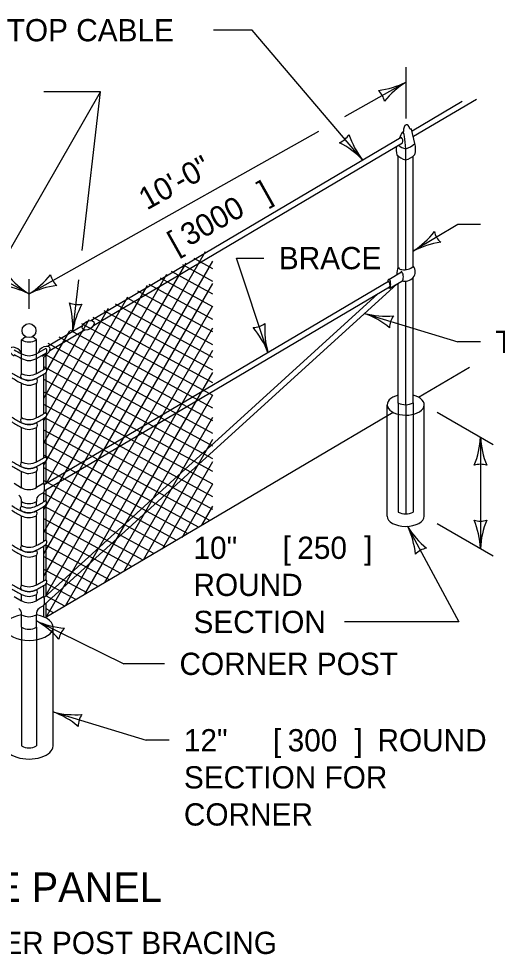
# Model space of a CAD drawing. Extents: x 49973.1 to 50021, y 49987.6 to 50015.4.
# Drawn here: x 49974.681 to 49975.97, y 50010.322 to 50012.844 of the extents above; entities that cross this region are included whole.
import ezdxf

# ---------------------------------------------------------------- set-up
doc = ezdxf.new("R2010")
doc.units = 0
for name, color, linetype in [('Level 1', 7, 'Continuous'), ('Level 2', 7, 'Continuous'), ('Level 3', 7, 'Continuous'), ('Level 4', 7, 'Continuous')]:
    doc.layers.add(name, color=color, linetype=linetype)

msp = doc.modelspace()

# ---------------------------------------------------------------- linework, layer by layer
at = {"layer": 'Level 1'}
for p, q in [((49975.7408, 50012.5423), (49975.8759, 50012.6222)), ((49975.7447, 50012.5273), (49975.9146, 50012.6278)), ((49975.7477, 50012.5078), (49975.7393, 50012.5467)), ((49974.875, 50012.0307), (49975.7109, 50012.5247)), ((49974.8821, 50012.0174), (49975.7149, 50012.5097)), ((49975.7235, 50012.1676), (49975.7235, 50012.4935)), ((49975.7035, 50012.1739), (49975.7035, 50012.4739)), ((49975.7435, 50012.1762), (49975.7435, 50012.4739)), ((49974.7487, 50011.4603), (49975.1844, 50012.2164)), ((49974.7487, 50011.4013), (49975.204, 50012.1903)), ((49974.7487, 50011.5207), (49975.1319, 50012.1857)), ((49975.204, 50012.1704), (49975.1532, 50012.1981)), ((49975.204, 50012.102), (49975.0927, 50012.1628)), ((49975.204, 50012.1362), (49975.1229, 50012.1804)), ((49975.6778, 50012.1417), (49975.7118, 50012.1618)), ((49974.7488, 50011.3416), (49975.204, 50012.1304)), ((49974.7493, 50011.5884), (49975.6773, 50012.1369)), ((49974.7553, 50011.5919), (49975.0798, 50012.1552)), ((49975.204, 50012.0679), (49975.0625, 50012.1451)), ((49975.6805, 50012.1181), (49975.7128, 50012.1372)), ((49975.7035, 50011.808), (49975.7035, 50012.1317)), ((49975.7235, 50011.8035), (49975.7235, 50012.1364)), ((49975.7435, 50011.8085), (49975.7435, 50012.1467)), ((49974.7487, 50011.6411), (49975.0275, 50012.1247)), ((49975.7002, 50012.1298), (49974.7491, 50011.264)), ((49974.7496, 50011.5712), (49975.6801, 50012.1211)), ((49975.204, 50011.9997), (49975.002, 50012.1098)), ((49975.204, 50012.0337), (49975.0322, 50012.1274)), ((49974.7487, 50011.7012), (49974.9752, 50012.0941)), ((49975.6481, 50012.1026), (49974.749, 50011.2842)), ((49975.204, 50011.9653), (49974.9718, 50012.0921)), ((49974.7487, 50011.7612), (49974.923, 50012.0636)), ((49974.7543, 50011.2911), (49975.204, 50012.0699)), ((49975.204, 50011.8966), (49974.9112, 50012.0567)), ((49975.204, 50011.9311), (49974.9415, 50012.0744)), ((49974.7487, 50011.8213), (49974.8709, 50012.0332)), ((49975.204, 50011.8626), (49974.881, 50012.0391)), ((49974.7543, 50011.2312), (49975.204, 50012.0106)), ((49974.8528, 50012.0167), (49974.7585, 50011.9608)), ((49974.8594, 50012.0051), (49974.7644, 50011.9489)), ((49975.204, 50011.8284), (49974.8507, 50012.0214)), ((49974.6885, 50011.9783), (49974.6991, 50011.9872)), ((49974.7285, 50011.9783), (49974.7179, 50011.9872)), ((49974.7568, 50011.8956), (49974.8186, 50012.0026)), ((49975.204, 50011.7603), (49974.7901, 50011.986)), ((49975.204, 50011.7942), (49974.8204, 50012.0037)), ((49974.6885, 50011.8867), (49974.6885, 50011.9783)), ((49974.7285, 50011.8869), (49974.7285, 50011.9783)), ((49974.7542, 50011.9552), (49974.7291, 50011.9408)), ((49975.204, 50011.7258), (49974.76, 50011.9685)), ((49974.753, 50011.9416), (49974.7292, 50011.9281)), ((49974.7543, 50011.9352), (49974.7487, 50011.9319)), ((49974.7487, 50011.8977), (49974.7487, 50011.9319)), ((49975.204, 50011.6919), (49974.7503, 50011.9397)), ((49974.7543, 50011.9013), (49974.7543, 50011.9352)), ((49974.8066, 50011.2615), (49975.204, 50011.9508)), ((49975.204, 50011.6574), (49974.7487, 50011.9062)), ((49974.7968, 50011.9048), (49974.8036, 50011.9165)), ((49975.7577, 50011.8237), (49975.895, 50011.9049)), ((49974.7487, 50011.7788), (49974.7487, 50011.8851)), ((49974.7543, 50011.7822), (49974.7543, 50011.8891)), ((49974.859, 50011.2925), (49975.204, 50011.8908)), ((49974.6885, 50011.7675), (49974.6885, 50011.8616)), ((49974.7285, 50011.7678), (49974.7285, 50011.8612)), ((49975.204, 50011.6238), (49974.7487, 50011.872)), ((49975.204, 50011.589), (49974.7487, 50011.8379)), ((49974.9119, 50011.3238), (49975.204, 50011.8303)), ((49975.204, 50011.5553), (49974.7487, 50011.8038)), ((49975.6735, 50011.5035), (49975.6735, 50011.8035)), ((49975.7735, 50011.5035), (49975.7735, 50011.8035)), ((49974.7524, 50011.2295), (49975.6894, 50011.7834)), ((49974.7487, 50011.6599), (49974.7487, 50011.7661)), ((49975.204, 50011.5209), (49974.7514, 50011.768)), ((49974.7543, 50011.663), (49974.7543, 50011.7702)), ((49974.9638, 50011.3538), (49975.204, 50011.7705)), ((49974.6885, 50011.6485), (49974.6885, 50011.7423)), ((49974.7285, 50011.649), (49974.7285, 50011.7422)), ((49975.1957, 50011.4916), (49974.7487, 50011.7354)), ((49975.0166, 50011.3855), (49975.204, 50011.7106)), ((49975.1655, 50011.4737), (49974.7485, 50011.7013)), ((49975.1355, 50011.456), (49974.7481, 50011.6673)), ((49974.7543, 50011.5914), (49974.7543, 50011.6514)), ((49975.1054, 50011.4382), (49974.748, 50011.6333)), ((49974.7487, 50011.5901), (49974.7487, 50011.6473)), ((49975.0686, 50011.4154), (49975.204, 50011.6503)), ((49974.6885, 50011.5799), (49974.6885, 50011.6234)), ((49974.7285, 50011.5802), (49974.7285, 50011.623)), ((49974.6683, 50011.5917), (49974.6885, 50011.5799)), ((49974.7481, 50011.5917), (49974.7284, 50011.5801)), ((49975.0754, 50011.4205), (49974.7494, 50011.5984)), ((49975.1208, 50011.4459), (49975.204, 50011.5902)), ((49974.7484, 50011.5671), (49974.7358, 50011.5597)), ((49974.7487, 50011.5415), (49974.7487, 50011.568)), ((49975.0451, 50011.4025), (49974.7487, 50011.5645)), ((49974.7543, 50011.5431), (49974.7543, 50011.5739)), ((49974.6885, 50011.5292), (49974.6885, 50011.5423)), ((49974.7285, 50011.5302), (49974.7285, 50011.5425)), ((49974.7487, 50011.4345), (49974.7487, 50011.5284)), ((49975.0162, 50011.3844), (49974.7501, 50011.5296)), ((49974.7543, 50011.438), (49974.7543, 50011.533)), ((49975.1746, 50011.4791), (49975.204, 50011.5301)), ((49974.6885, 50011.4234), (49974.6885, 50011.504)), ((49974.7285, 50011.4238), (49974.7285, 50011.5044)), ((49974.9862, 50011.3666), (49974.7488, 50011.4962)), ((49974.9561, 50011.3488), (49974.7488, 50011.4619)), ((49974.9251, 50011.3316), (49974.7535, 50011.4251)), ((49974.7543, 50011.3317), (49974.7543, 50011.4257)), ((49974.7487, 50011.3282), (49974.7487, 50011.422)), ((49974.6885, 50011.3172), (49974.6885, 50011.3983)), ((49974.7285, 50011.3173), (49974.7285, 50011.398)), ((49974.895, 50011.3138), (49974.7489, 50011.3936)), ((49974.8649, 50011.296), (49974.7487, 50011.3594)), ((49974.7487, 50011.2849), (49974.7487, 50011.3157)), ((49974.7543, 50011.2891), (49974.7543, 50011.3195)), ((49974.8349, 50011.2783), (49974.7557, 50011.3214)), ((49974.6683, 50011.2865), (49974.6885, 50011.2747)), ((49974.6885, 50011.2746), (49974.6885, 50011.292)), ((49974.7481, 50011.2865), (49974.7284, 50011.2749)), ((49974.7285, 50011.275), (49974.7285, 50011.2919)), ((49974.8047, 50011.2604), (49974.7536, 50011.2884)), ((49974.7484, 50011.2619), (49974.7361, 50011.2546)), ((49974.7487, 50011.2318), (49974.7487, 50011.2628)), ((49974.7543, 50011.2313), (49974.7543, 50011.2686)), ((49974.7747, 50011.2427), (49974.7546, 50011.2536)), ((49974.6885, 50011.2035), (49974.6885, 50011.2371)), ((49974.7285, 50011.2035), (49974.7285, 50011.2373)), ((49974.7735, 50010.8835), (49974.7735, 50011.2035))]:
    msp.add_line(p, q, dxfattribs=at)
msp.add_circle((49974.7085, 50012.0034), 0.0188, dxfattribs=at)
for centre, radius, start, end in [((49975.7183, 50012.5302), 0.00892, 101.7957, 120.997), ((49975.7362, 50012.5502), 0.00296, 237.4787, 300.0955), ((49975.7463, 50012.5611), 0.016, 237.5014, 244.0751), ((49975.704, 50012.5148), 0.0121, 334.8948, 54.9962), ((49975.7611, 50012.4926), 0.0633, 173.4419, 193.7131), ((49975.7356, 50012.5413), 0.0492, 230.34, 255.8294), ((49975.7101, 50012.5439), 0.0521, 284.9196, 316.2234), ((49975.7004, 50012.4928), 0.0496, 342.4177, 17.5896), ((49975.7356, 50012.5113), 0.0492, 223.0922, 255.8294), ((49975.7101, 50012.5139), 0.0521, 284.9189, 316.2234), ((49975.7312, 50012.1585), 0.0317, 150.1806, 187.0158), ((49975.7132, 50012.178), 0.0102, 201.7798, 270.84), ((49975.7193, 50012.205), 0.0377, 260.9359, 311.2879), ((49975.7255, 50012.1621), 0.0237, 320.3364, 38.1248), ((49975.6879, 50012.1365), 0.0127, 160.71, 183.758), ((49975.6664, 50012.1268), 0.0149, 337.4474, 42.724), ((49975.7203, 50012.1672), 0.0309, 255.9694, 319.2134), ((49975.6835, 50012.121), 0.00599, 192.716, 219.6559), ((49974.7085, 50012.0141), 0.041, 240.8333, 299.1667), ((49974.7481, 50011.9489), 0.00871, 303.6425, 46.3366), ((49974.6963, 50011.8805), 0.0105, 142.1576, 216.9265), ((49974.7481, 50011.8952), 0.00871, 312.91, 46.3619), ((49974.7209, 50011.8678), 0.0105, 323.0735, 37.8424), ((49975.7231, 50011.8481), 0.0445, 244.0215, 297.414), ((49974.748, 50011.7762), 0.00871, 312.91, 46.3366), ((49974.6962, 50011.7615), 0.0105, 142.1576, 216.9265), ((49974.7208, 50011.7488), 0.0105, 323.0735, 37.8424), ((49974.7479, 50011.6572), 0.00871, 312.91, 46.3366), ((49974.6961, 50011.6425), 0.0105, 142.1576, 216.9265), ((49974.7207, 50011.6298), 0.0105, 323.0735, 37.8424), ((49974.7082, 50011.6159), 0.041, 239.6098, 300.3902), ((49974.7159, 50011.579), 0.0346, 339.9145, 21.52), ((49974.6705, 50011.5448), 0.0181, 352.1171, 54.7359), ((49974.7466, 50011.545), 0.0181, 125.2641, 187.8829), ((49974.6954, 50011.5234), 0.0105, 142.1576, 216.9265), ((49974.7084, 50011.5782), 0.041, 240.8333, 299.1667), ((49974.7472, 50011.5381), 0.00871, 312.91, 46.3366), ((49974.72, 50011.5107), 0.0105, 323.0735, 37.8424), ((49974.7481, 50011.432), 0.00871, 312.91, 46.3366), ((49974.6963, 50011.4173), 0.0105, 142.1576, 216.9265), ((49974.7209, 50011.4046), 0.0105, 323.0735, 37.8424), ((49974.7481, 50011.3257), 0.00871, 312.91, 46.3366), ((49974.6963, 50011.311), 0.0105, 142.1576, 216.9265), ((49974.7209, 50011.2983), 0.0105, 323.0735, 37.8424), ((49974.7082, 50011.3107), 0.041, 239.6098, 299.4812), ((49974.7159, 50011.2738), 0.0346, 339.9145, 21.52), ((49974.6705, 50011.2396), 0.0181, 352.1171, 54.7359), ((49974.7466, 50011.2398), 0.0181, 125.2641, 187.8829), ((49974.7084, 50011.273), 0.041, 240.8333, 299.1667), ((49974.7085, 50011.2394), 0.041, 240.8333, 299.1667)]:
    msp.add_arc(centre, radius, start, end, dxfattribs=at)
for centre, major_axis, ratio, start_param, end_param in [((49975.7262, 50012.5413), (-0.0001, 0.0176), 0.514964, 5.08229, 7.879337), ((49975.7123, 50012.1495), (-0.0005, 0.0123), 0.386165, 3.161585, 6.68335), ((49975.6782, 50012.1294), (-0.0005, 0.0123), 0.386165, 3.161585, 6.68335), ((49974.6719, 50011.9456), (-0.015, 0.009), 0.610393, 3.559041, 7.997344), ((49974.7495, 50011.9482), (0.015, 0.009), 0.610393, 4.569027, 9.084095), ((49974.7495, 50011.9482), (0.015, 0.009), 0.610393, 3.972008, 4.569027), ((49975.7235, 50011.8035), (0.05, 0), 0.560136, 1.982076, 7.431596), ((49975.7235, 50011.5035), (0.05, 0), 0.560136, 3.141593, 6.283185), ((49974.7085, 50011.2035), (0.065, 0), 0.543263, 1.885894, 7.541224), ((49974.7085, 50010.8835), (-0.065, 0), 0.54167, 0, 3.141593)]:
    msp.add_ellipse(centre, major_axis=major_axis, ratio=ratio, start_param=start_param, end_param=end_param, dxfattribs=at)
msp.add_ellipse((49974.8678, 50012.0178), major_axis=(0.015, 0.009), ratio=0.610393, dxfattribs=at)
for points in [[(49975.7235, 50012.4935), (49975.714, 50012.5373), (49975.7067, 50012.5222)], [(49975.7171, 50012.5408), (49975.7169, 50012.5395), (49975.7164, 50012.5389)], [(49974.6683, 50011.9516), (49974.6885, 50011.9408), (49974.7085, 50011.9355), (49974.7291, 50011.9408)], [(49974.6684, 50011.9389), (49974.6886, 50011.9281), (49974.7086, 50011.9228), (49974.7292, 50011.9281)], [(49974.663, 50011.8888), (49974.6885, 50011.8742), (49974.7085, 50011.8689), (49974.7291, 50011.8742)], [(49974.754, 50011.8888), (49974.7285, 50011.8742), (49974.7085, 50011.8689), (49974.6879, 50011.8742)], [(49974.7541, 50011.9015), (49974.7286, 50011.8869), (49974.7086, 50011.8816), (49974.688, 50011.8869)], [(49974.6631, 50011.8761), (49974.6886, 50011.8615), (49974.7086, 50011.8562), (49974.7292, 50011.8615)], [(49974.754, 50011.7825), (49974.7285, 50011.7679), (49974.7085, 50011.7626), (49974.6879, 50011.7679)], [(49974.6629, 50011.7698), (49974.6884, 50011.7552), (49974.7084, 50011.7499), (49974.729, 50011.7552)], [(49974.663, 50011.7571), (49974.6885, 50011.7425), (49974.7085, 50011.7372), (49974.7291, 50011.7425)], [(49974.7539, 50011.7698), (49974.7284, 50011.7552), (49974.7084, 50011.7499), (49974.6878, 50011.7552)], [(49974.7539, 50011.6635), (49974.7284, 50011.6489), (49974.7084, 50011.6436), (49974.6878, 50011.6489)], [(49974.6628, 50011.6508), (49974.6883, 50011.6362), (49974.7083, 50011.6309), (49974.7289, 50011.6362)], [(49974.6629, 50011.6381), (49974.6884, 50011.6235), (49974.7084, 50011.6182), (49974.729, 50011.6235)], [(49974.7538, 50011.6508), (49974.7283, 50011.6362), (49974.7083, 50011.6309), (49974.6877, 50011.6362)], [(49974.6621, 50011.5317), (49974.6876, 50011.5171), (49974.7076, 50011.5118), (49974.7282, 50011.5171)], [(49974.7531, 50011.5317), (49974.7276, 50011.5171), (49974.7076, 50011.5118), (49974.687, 50011.5171)], [(49974.7532, 50011.5444), (49974.7277, 50011.5298), (49974.7077, 50011.5245), (49974.6871, 50011.5298)], [(49974.6622, 50011.519), (49974.6877, 50011.5044), (49974.7077, 50011.4991), (49974.7283, 50011.5044)], [(49974.663, 50011.4256), (49974.6885, 50011.411), (49974.7085, 50011.4057), (49974.7291, 50011.411)], [(49974.754, 50011.4256), (49974.7285, 50011.411), (49974.7085, 50011.4057), (49974.6879, 50011.411)], [(49974.7541, 50011.4383), (49974.7286, 50011.4237), (49974.7086, 50011.4184), (49974.688, 50011.4237)], [(49974.6631, 50011.4129), (49974.6886, 50011.3983), (49974.7086, 50011.393), (49974.7292, 50011.3983)], [(49974.7541, 50011.332), (49974.7286, 50011.3174), (49974.7086, 50011.3121), (49974.688, 50011.3174)], [(49974.663, 50011.3193), (49974.6885, 50011.3047), (49974.7085, 50011.2994), (49974.7291, 50011.3047)], [(49974.6631, 50011.3066), (49974.6886, 50011.292), (49974.7086, 50011.2867), (49974.7292, 50011.292)], [(49974.754, 50011.3193), (49974.7285, 50011.3047), (49974.7085, 50011.2994), (49974.6879, 50011.3047)]]:
    msp.add_spline(points, degree=3, dxfattribs=at)
at = {"layer": 'Level 3'}
for p, q in [((49975.3101, 50012.8135), (49975.2054, 50012.8135)), ((49975.6074, 50012.4636), (49975.3101, 50012.8135)), ((49975.7243, 50012.5751), (49975.7243, 50012.7137)), ((49975.5593, 50012.5808), (49975.7241, 50012.6736)), ((49974.6381, 50012.188), (49974.9013, 50012.6472)), ((49974.9013, 50012.6472), (49974.7483, 50012.6472)), ((49974.8514, 50012.2197), (49974.9013, 50012.6472)), ((49974.8817, 50012.1996), (49975.4896, 50012.5416)), ((49975.8636, 50012.2893), (49975.7435, 50012.2176)), ((49975.9248, 50012.2893), (49975.8636, 50012.2893)), ((49974.7085, 50012.1022), (49974.8817, 50012.1996)), ((49975.3522, 50011.9447), (49975.268, 50012.199)), ((49975.268, 50012.199), (49975.3416, 50012.199)), ((49974.6013, 50012.1629), (49974.7085, 50012.1022)), ((49974.7085, 50012.0622), (49974.7085, 50012.1422)), ((49974.8422, 50012.1402), (49974.8259, 50012.0008)), ((49975.6126, 50012.05), (49975.8636, 50011.9735)), ((49975.9248, 50011.9735), (49975.8636, 50011.9735)), ((49975.8082, 50011.7836), (49975.9595, 50011.6963)), ((49975.9248, 50011.7164), (49975.9248, 50011.4164)), ((49975.7286, 50011.4757), (49975.8669, 50011.2179)), ((49975.8082, 50011.4836), (49975.9595, 50011.3963)), ((49974.7285, 50011.2206), (49974.9642, 50011.105)), ((49975.8669, 50011.2179), (49975.559, 50011.2179)), ((49975.074, 50011.105), (49974.9642, 50011.105)), ((49974.7735, 50010.9754), (49975.0246, 50010.8989)), ((49975.0858, 50010.8989), (49975.0246, 50010.8989))]:
    msp.add_line(p, q, dxfattribs=at)
for centre, radius, start, end in [((49975.6234, 50012.8718), 0.2223, 276.8182, 297.0017), ((49975.8485, 50012.4765), 0.233, 122.1895, 141.4393), ((49975.6126, 50012.6109), 0.0548, 11.501, 47.2234), ((49975.5236, 50012.5606), 0.0548, 292.973, 328.6954), ((49975.4389, 50012.3027), 0.233, 43.6615, 62.9114), ((49975.7815, 50012.6019), 0.2223, 198.2902, 218.4737), ((49975.6161, 50012.4127), 0.233, 303.1681, 322.418), ((49975.8542, 50012.2824), 0.0548, 192.4796, 228.202), ((49975.8479, 50012.0213), 0.2223, 97.7968, 117.9804), ((49974.8259, 50012.2911), 0.2223, 217.9705, 238.154), ((49974.5844, 50012.2994), 0.233, 302.1914, 321.4413), ((49974.8203, 50012.1651), 0.0548, 191.503, 227.2253), ((49974.604, 50011.894), 0.233, 63.3418, 82.5916), ((49974.8095, 50011.9041), 0.2223, 96.8201, 117.0037), ((49974.84, 50012.1282), 0.0548, 245.8148, 281.5372), ((49974.5933, 50012.015), 0.233, 356.5033, 15.7531), ((49975.0457, 50011.9672), 0.2223, 151.132, 171.3155), ((49975.5363, 50011.8412), 0.2223, 49.7405, 69.924), ((49975.6725, 50012.2752), 0.233, 255.1118, 274.3617), ((49975.7348, 50012.011), 0.0548, 144.4233, 180.1457), ((49975.3119, 50012.0665), 0.0548, 270.449, 306.1713), ((49975.1349, 50011.8607), 0.233, 21.1375, 40.3873), ((49975.566, 50012.0058), 0.2223, 175.7662, 195.9497), ((49975.7027, 50011.7255), 0.2223, 337.456, 357.6395), ((49976.1576, 50011.7278), 0.233, 182.8273, 202.0772), ((49975.9248, 50011.5881), 0.0548, 72.1388, 107.8612), ((49975.5285, 50011.3788), 0.2223, 5.6616, 25.8451), ((49975.9283, 50011.5958), 0.233, 211.0329, 230.2828), ((49975.9248, 50011.5446), 0.0548, 252.1388, 287.8612), ((49975.6921, 50011.4049), 0.233, 2.8273, 22.0772), ((49976.147, 50011.4072), 0.2223, 157.456, 177.6395), ((49975.7892, 50011.3627), 0.0548, 100.3444, 136.0668), ((49974.6199, 50011.0266), 0.2223, 40.5672, 60.7507), ((49974.8235, 50011.4333), 0.233, 245.9385, 265.1884), ((49974.8429, 50011.1626), 0.0548, 135.25, 170.9724), ((49974.6972, 50010.7666), 0.2223, 49.7405, 69.924), ((49974.8334, 50011.2006), 0.233, 255.1118, 274.3617), ((49974.8957, 50010.9364), 0.0548, 144.4233, 180.1457)]:
    msp.add_arc(centre, radius, start, end, dxfattribs=at)
at = {"layer": 'Level 4'}
for p, q in [((49975.7035, 50011.808), (49975.7035, 50011.5137)), ((49975.7235, 50011.8035), (49975.7235, 50011.5091)), ((49975.7435, 50011.8085), (49975.7435, 50011.5142)), ((49974.6885, 50011.2035), (49974.6885, 50010.8835)), ((49974.7285, 50011.2035), (49974.7285, 50010.8835))]:
    msp.add_line(p, q, dxfattribs=at)
for centre, radius, start, end in [((49975.723, 50011.5538), 0.0445, 244.0215, 297.414), ((49974.7085, 50010.9194), 0.041, 240.8333, 299.1667)]:
    msp.add_arc(centre, radius, start, end, dxfattribs=at)

# ---------------------------------------------------------------- texts
at = {"layer": 'Level 2'}
for s, height, p in [('TOP CABLE', 0.06, (49974.6485, 50012.7835)), ('BRACE', 0.06, (49975.3816, 50012.169)), ('TRUSS ROD', 0.06, (49975.9648, 50011.9435)), ('[', 0.06, (49975.3917, 50011.3879)), (']', 0.06, (49975.6114, 50011.3879)), ('10" ', 0.06, (49975.1517, 50011.3879)), ('250', 0.06, (49975.4314, 50011.3879)), ('ROUND', 0.06, (49975.1517, 50011.2879)), ('SECTION', 0.06, (49975.1517, 50011.1879)), ('CORNER POST', 0.06, (49975.114, 50011.075)), ('12" ', 0.06, (49975.1258, 50010.8689)), ('[', 0.06, (49975.3658, 50010.8689)), ('300', 0.06, (49975.4054, 50010.8689)), (']', 0.06, (49975.5854, 50010.8689)), (' ROUND', 0.06, (49975.6251, 50010.8689)), ('SECTION FOR', 0.06, (49975.1258, 50010.7689)), ('CORNER', 0.06, (49975.1258, 50010.6689)), ('DOUBLE PANEL', 0.08, (49974.246, 50010.4626)), ('PULL POST AND CORNER POST BRACING', 0.06, (49973.7449, 50010.3226))]:
    msp.add_text(s, height=height, dxfattribs=at).set_placement(p)
for s, p in [('10\'-0"', (49975.0261, 50012.327)), (']', (49975.348, 50012.347)), ('3000', (49975.1387, 50012.2296)), ('[', (49975.104, 50012.2102))]:
    msp.add_text(s, height=0.06, rotation=29.2705, dxfattribs=at).set_placement(p)

doc.saveas('drawing.dxf')
